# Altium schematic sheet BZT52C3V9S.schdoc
size 127 x 101 mm
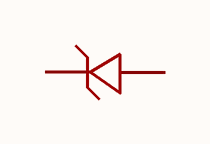
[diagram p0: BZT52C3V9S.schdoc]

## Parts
ZD?  bzt52c3v9s_c22609  [SOD-323_L1.8-W1.3-LS2.5-RD]  (value not drawn)

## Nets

Not connected (* = marked no-connect by the designer): ZD? 1(K) 2(A)

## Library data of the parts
ZD? = bzt52c3v9s_c22609: 二极管配置:1个独立式;稳压值(标称值):3.9V;稳压值(范围值):3.7V~4.1V;耗散功率(Pd):200mW;; Manufacturer: CJ(江苏长电/长晶); AddInBom: yes; ModelId: db63db13d9e342eb939127d413d6200b; ModelTransform: 104.3305,51.181,0,0,0,0,0,-0.004,0; Diode Configuration: 1个独立式; Zener Voltage(Nom): 3.9V; Reverse Leakage Current (Ir): 3uA@1V; Pd - Power Dissipation: 200mW; Impedance(Zzt): 90Ω; Impedance(Zzk): 600Ω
